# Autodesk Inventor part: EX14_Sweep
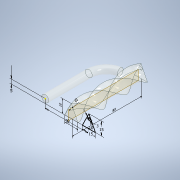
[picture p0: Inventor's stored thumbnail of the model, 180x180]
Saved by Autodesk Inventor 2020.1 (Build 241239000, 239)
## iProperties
Created: 2019-10
Part Number: EX14_Sweep
Material: Nickel-Copper Alloy 400
Document SubType Name: Modeling
Designer: Synergysoft Dell02
Density: 8.83 g/cm^3
Appearance: Clear
Author: Synergysoft Dell02
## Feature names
1. Sweep1
2. Sweep2
## Parameters: d2 = 80 deg, d3 = 8 mm, d4 = 0, d5 = 0, d6 = 15 mm, d7 = 5 mm, d8 = 15 mm, d11 = 0, d12 = 360 deg, d14 = 3 mm, d16 = 5.57743 mm, d17 = 1.93905 mm, d19 = 10.01594 mm, d20 = 3 mm, d21 = 0, d23 = 15 mm, d24 = 4.76607 mm, d25 = 15 mm
